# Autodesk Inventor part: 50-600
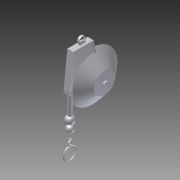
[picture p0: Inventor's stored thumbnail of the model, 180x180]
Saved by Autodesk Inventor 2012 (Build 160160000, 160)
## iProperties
Created: 2004-11
Part Number: 50-600
Document SubType Name: Modeling
Designer: Autodesk, Inc.
Manufacturer: Standard
Standards Organization: Custom
Description: Tool Balancer,  Zero Gravity, 0.8~2.6 LBS
Catalog Web Link: http://www.parker.com/ead/cm1.asp?cmid=809
Vendor: PARKER IPS
Mass: 622.981 g
Surface Area: 555.93 cm^2
Volume: 622.981 cm^3
Density: 1 g/cm^3
Material: Default
CAGE: 1LJX3
Dept. ID: Product Design
Description #2: ---
Finish #1: ---
Finish #2: ---
Material ID: ---
Project Number: ---
Description: "Zero Gravity" Tool Balancer
Order Number: 50-600
Selection: "Zero Gravity" Tool Balancer
Supplier: Parker Hannifin Corp., Industrial Profile Systems Div.
Author: Autodesk, Inc.
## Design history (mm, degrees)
feature "Base1"
workpoint "Work Point1"
workpoint "Work Point2"
workaxis "Work Axis3"
workpoint "Work Point3"
workaxis "Work Axis5"
  workplane "Work Plane2"
body "Solid1"
other parameters: "d0" = 90 deg, "d1" = 0, "d2" = 0
